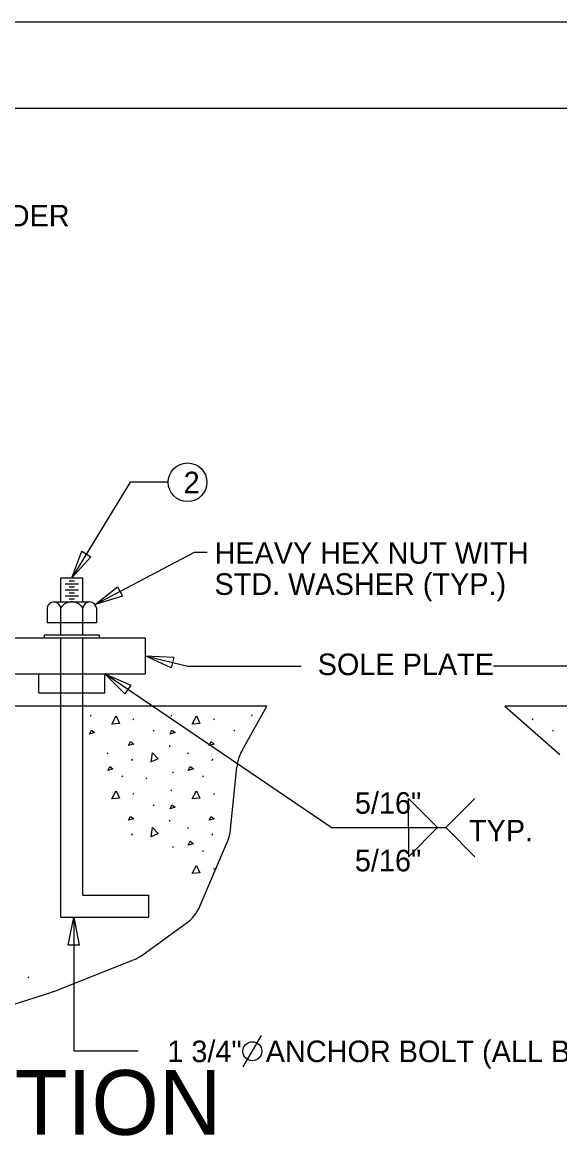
# Model space of a CAD drawing. Extents: x -125.5 to -89.4, y -5.1 to 16.9.
# Drawn here: x -115.57 to -112.46, y 10.48 to 16.93 of the extents above; entities that cross this region are included whole.
import ezdxf

# ---------------------------------------------------------------- set-up
doc = ezdxf.new("R2010")
doc.units = 0
for name, color, linetype in [('BR_AUTO DIMENSION', 7, 'Continuous'), ('BR_BORDER LINES', 7, 'Continuous'), ('BR_CONCRETE', 7, 'Continuous'), ('BR_REBAR', 7, 'Continuous'), ('BR_STRUCTURAL STEEL', 7, 'Continuous'), ('BR_TEXT', 7, 'Continuous'), ('Default', 7, 'Continuous'), ('Level 31', 7, 'Continuous')]:
    doc.layers.add(name, color=color, linetype=linetype)

msp = doc.modelspace()

# ---------------------------------------------------------------- linework, layer by layer
at = {"layer": 'BR_AUTO DIMENSION'}
for p, q in [((-114.9467, 14.269), (-115.2844, 13.7148)), ((-114.7256, 14.269), (-114.9467, 14.269)), ((-115.1496, 13.5602), (-114.5741, 13.864)), ((-114.5741, 13.864), (-114.5007, 13.864)), ((-114.8585, 13.2641), (-114.6122, 13.2038)), ((-113.7814, 12.2684), (-115.0933, 13.1599)), ((-114.6122, 13.2038), (-113.9558, 13.2038)), ((-112.0009, 13.2038), (-112.8408, 13.2038)), ((-113.1645, 12.2684), (-113.3326, 12.4365)), ((-113.3326, 12.2684), (-113.3326, 12.4365)), ((-112.9495, 12.4365), (-113.1176, 12.2684)), ((-113.7814, 12.2684), (-113.1176, 12.2684)), ((-113.1645, 12.2684), (-113.3326, 12.1003)), ((-113.3326, 12.2684), (-113.3326, 12.1003)), ((-113.1176, 12.2684), (-112.9495, 12.1003)), ((-115.2733, 11.7505), (-115.2733, 10.9757)), ((-115.2733, 10.9757), (-114.8991, 10.9757))]:
    msp.add_line(p, q, dxfattribs=at)
for points in [[(-115.1732, 13.8374), (-115.2844, 13.7148), (-115.2265, 13.8699)], [(-114.9913, 13.6085), (-115.1496, 13.5602), (-115.0204, 13.6637)], [(-114.7083, 13.1947), (-114.8585, 13.2641), (-114.6933, 13.2554)], [(-114.9764, 13.0427), (-115.0933, 13.1599), (-114.9413, 13.0944)], [(-115.3045, 11.588), (-115.2733, 11.7505), (-115.242, 11.588)]]:
    msp.add_lwpolyline(points, close=True, dxfattribs=at)
msp.add_circle((-114.6135, 14.269), 0.1121, dxfattribs=at)
at = {"layer": 'BR_BORDER LINES'}
msp.add_line((-90.0334, 16.4338), (-123.6994, 16.4338), dxfattribs=at)
at = {"layer": 'BR_CONCRETE'}
for p, q in [((-114.1549, 12.9727), (-119.7474, 12.9727)), ((-110.9149, 12.9727), (-112.7753, 12.9727))]:
    msp.add_line(p, q, dxfattribs=at)
at = {"layer": 'BR_REBAR'}
for p, q in [((-115.3481, 13.7148), (-115.2207, 13.7148)), ((-115.3481, 13.5762), (-115.3481, 13.7148)), ((-115.3226, 13.6802), (-115.2462, 13.6802)), ((-115.3003, 13.6975), (-115.2685, 13.6975)), ((-115.2207, 13.5762), (-115.2207, 13.7148)), ((-115.3226, 13.6455), (-115.2462, 13.6455)), ((-115.3226, 13.6109), (-115.2462, 13.6109)), ((-115.3003, 13.6628), (-115.2685, 13.6628)), ((-115.3003, 13.6282), (-115.2685, 13.6282)), ((-115.3879, 13.5762), (-115.1809, 13.5762)), ((-115.3003, 13.5935), (-115.2685, 13.5935)), ((-115.4277, 13.5415), (-115.4277, 13.4549)), ((-115.3481, 13.3855), (-115.3481, 13.5415)), ((-115.2207, 13.3855), (-115.2207, 13.5415)), ((-115.1411, 13.5415), (-115.1411, 13.4549)), ((-115.1411, 13.4549), (-115.4277, 13.4549)), ((-115.4436, 13.3855), (-115.4436, 13.3682)), ((-115.4436, 13.3855), (-115.1251, 13.3855)), ((-115.4436, 13.3682), (-115.1251, 13.3682)), ((-115.3481, 13.1599), (-115.3481, 13.3682)), ((-115.2207, 13.1599), (-115.2207, 13.3682)), ((-115.1251, 13.3855), (-115.1251, 13.3682)), ((-115.3481, 12.9727), (-115.3481, 13.1599)), ((-115.2207, 12.9727), (-115.2207, 13.1599)), ((-115.3481, 11.7505), (-115.3481, 12.9727)), ((-115.2207, 11.8779), (-115.2207, 12.9727)), ((-115.2207, 11.8779), (-114.8388, 11.8779)), ((-114.8388, 11.7505), (-114.8388, 11.8779)), ((-115.3481, 11.7505), (-114.8388, 11.7505))]:
    msp.add_line(p, q, dxfattribs=at)
for centre, major_axis, start_param, end_param in [((-115.3879, 13.5318), (0, 0.0444), 4.933703, 7.632667), ((-115.2844, 13.4895), (0, 0.0867), 5.35589, 7.210481), ((-115.1809, 13.5318), (0, 0.0444), 4.933703, 7.632667)]:
    msp.add_ellipse(centre, major_axis=major_axis, ratio=0.918783, start_param=start_param, end_param=end_param, dxfattribs=at)
at = {"layer": 'BR_STRUCTURAL STEEL'}
for p, q in [((-118.1036, 13.3682), (-114.8585, 13.3682)), ((-114.8585, 13.3682), (-114.8585, 13.1599)), ((-118.1036, 13.1599), (-114.8585, 13.1599)), ((-115.4755, 13.0491), (-115.4755, 13.1599)), ((-115.0933, 13.0491), (-115.0933, 13.1599)), ((-115.4755, 13.0491), (-115.0933, 13.0491))]:
    msp.add_line(p, q, dxfattribs=at)
at = {"layer": 'BR_TEXT'}
msp.add_line((-114.2907, 10.8823), (-114.1857, 11.0642), dxfattribs=at)
msp.add_circle((-114.2382, 10.9732), 0.055, dxfattribs=at)
at = {"layer": 'Default'}
for p, q in [((-114.2979, 12.7146), (-114.1549, 12.9727)), ((-112.7753, 12.9727), (-112.4566, 12.6913)), ((-115.1751, 12.9144), (-115.1714, 12.9227)), ((-114.9277, 12.8931), (-114.924, 12.9014)), ((-114.7084, 12.9144), (-114.7047, 12.9227)), ((-114.461, 12.8931), (-114.4573, 12.9014)), ((-114.2418, 12.9144), (-114.2381, 12.9227)), ((-112.6148, 12.8931), (-112.6111, 12.9014)), ((-114.812, 12.8339), (-114.8083, 12.8283)), ((-114.3454, 12.8339), (-114.3417, 12.8283)), ((-112.4991, 12.8339), (-112.4954, 12.8283)), ((-114.7185, 12.7452), (-114.7176, 12.7368)), ((-115.0775, 12.6961), (-115.0738, 12.7044)), ((-114.9369, 12.6581), (-114.9332, 12.6665)), ((-114.6109, 12.6961), (-114.6072, 12.7044)), ((-114.4703, 12.6581), (-114.4666, 12.6665)), ((-114.7014, 12.5925), (-114.6977, 12.5869)), ((-114.3637, 12.2606), (-114.3279, 12.6183)), ((-114.9935, 12.5689), (-114.9898, 12.5634)), ((-114.8528, 12.5508), (-114.849, 12.5592)), ((-114.5268, 12.5689), (-114.5231, 12.5634)), ((-114.9277, 12.4602), (-114.924, 12.4686)), ((-114.7084, 12.4815), (-114.7047, 12.4898)), ((-114.461, 12.4602), (-114.4573, 12.4686)), ((-114.812, 12.401), (-114.8083, 12.3955)), ((-114.7185, 12.3123), (-114.7176, 12.304)), ((-114.6109, 12.2632), (-114.6072, 12.2715)), ((-114.9369, 12.2253), (-114.9332, 12.2336)), ((-114.4703, 12.2253), (-114.4666, 12.2336)), ((-114.7014, 12.1596), (-114.6977, 12.1541)), ((-114.5396, 11.8175), (-114.3824, 12.1877)), ((-114.5268, 12.1361), (-114.5231, 12.1305)), ((-114.461, 12.0274), (-114.4573, 12.0357)), ((-114.8713, 11.533), (-114.6231, 11.7128)), ((-115.3892, 11.3199), (-114.926, 11.503)), ((-115.5367, 11.3975), (-115.533, 11.4059)), ((-116.1074, 11.0907), (-115.4053, 11.3142))]:
    msp.add_line(p, q, dxfattribs=at)
for points in [[(-115.0526, 12.8681), (-115.0276, 12.9153), (-115.0081, 12.8718), (-115.0516, 12.8681)], [(-114.5859, 12.8681), (-114.5609, 12.9153), (-114.5415, 12.8718), (-114.585, 12.8681)], [(-115.1816, 12.8098), (-115.1705, 12.833), (-115.152, 12.8191), (-115.1816, 12.8098)], [(-114.7149, 12.8098), (-114.7038, 12.833), (-114.6853, 12.8191), (-114.7149, 12.8098)], [(-114.9552, 12.7437), (-114.9441, 12.7668), (-114.9256, 12.753), (-114.9552, 12.7437)], [(-114.4886, 12.7437), (-114.4775, 12.7668), (-114.459, 12.753), (-114.4886, 12.7437)], [(-114.8244, 12.6486), (-114.8171, 12.7014), (-114.7839, 12.6672), (-114.8235, 12.6489)], [(-115.0757, 12.5989), (-115.0646, 12.6221), (-115.0461, 12.6082), (-115.0757, 12.5989)], [(-114.609, 12.5989), (-114.5979, 12.6221), (-114.5794, 12.6082), (-114.609, 12.5989)], [(-115.0526, 12.4353), (-115.0276, 12.4824), (-115.0081, 12.439), (-115.0516, 12.4353)], [(-114.5859, 12.4353), (-114.5609, 12.4824), (-114.5415, 12.439), (-114.585, 12.4353)], [(-114.7149, 12.377), (-114.7038, 12.4001), (-114.6853, 12.3862), (-114.7149, 12.377)], [(-114.9552, 12.3109), (-114.9441, 12.334), (-114.9256, 12.3201), (-114.9552, 12.3109)], [(-114.4886, 12.3109), (-114.4775, 12.334), (-114.459, 12.3201), (-114.4886, 12.3109)], [(-114.8244, 12.2157), (-114.8171, 12.2686), (-114.7839, 12.2344), (-114.8235, 12.216)], [(-114.609, 12.1661), (-114.5979, 12.1892), (-114.5794, 12.1753), (-114.609, 12.1661)], [(-114.5859, 12.0024), (-114.5609, 12.0496), (-114.5415, 12.0061), (-114.585, 12.0024)]]:
    msp.add_lwpolyline(points, dxfattribs=at)
for centre, start, end in [((-114.0792, 12.5934), 151.01619, 174.28906), ((-114.6125, 12.2855), 336.98375, 354.28906), ((-114.7697, 11.9153), 305.91455, 336.98375), ((-115.0179, 11.7355), 291.57303, 305.91455), ((-115.4811, 11.5524), 287.65574, 291.57303)]:
    msp.add_arc(centre, 0.25, start, end, dxfattribs=at)
at = {"layer": 'Level 31'}
msp.add_line((-89.5328, 16.9339), (-125.5328, 16.9339), dxfattribs=at)

# ---------------------------------------------------------------- texts
at = {"layer": 'BR_AUTO DIMENSION'}
msp.add_text('2', height=0.125, dxfattribs=at).set_placement((-114.6361, 14.2054))
at = {"layer": 'BR_TEXT'}
for s, height, p in [('L GIRDER', 0.125, (-116.0864, 15.7511)), ('HEAVY HEX NUT WITH ', 0.125, (-114.4574, 13.7969)), ('STD. WASHER (TYP.)', 0.125, (-114.4574, 13.6168)), ('SOLE PLATE', 0.125, (-113.8593, 13.152)), ('5/16"', 0.125, (-113.6438, 12.3489)), ('TYP.', 0.125, (-112.9827, 12.1886)), ('5/16"', 0.125, (-113.6438, 12.0154)), ('1 3/4"   ANCHOR BOLT (ALL BENTS)', 0.125, (-114.7308, 10.91)), ('END ELEVATION', 0.375, (-118.4304, 10.4891))]:
    msp.add_text(s, height=height, dxfattribs=at).set_placement(p)

doc.saveas('drawing.dxf')
